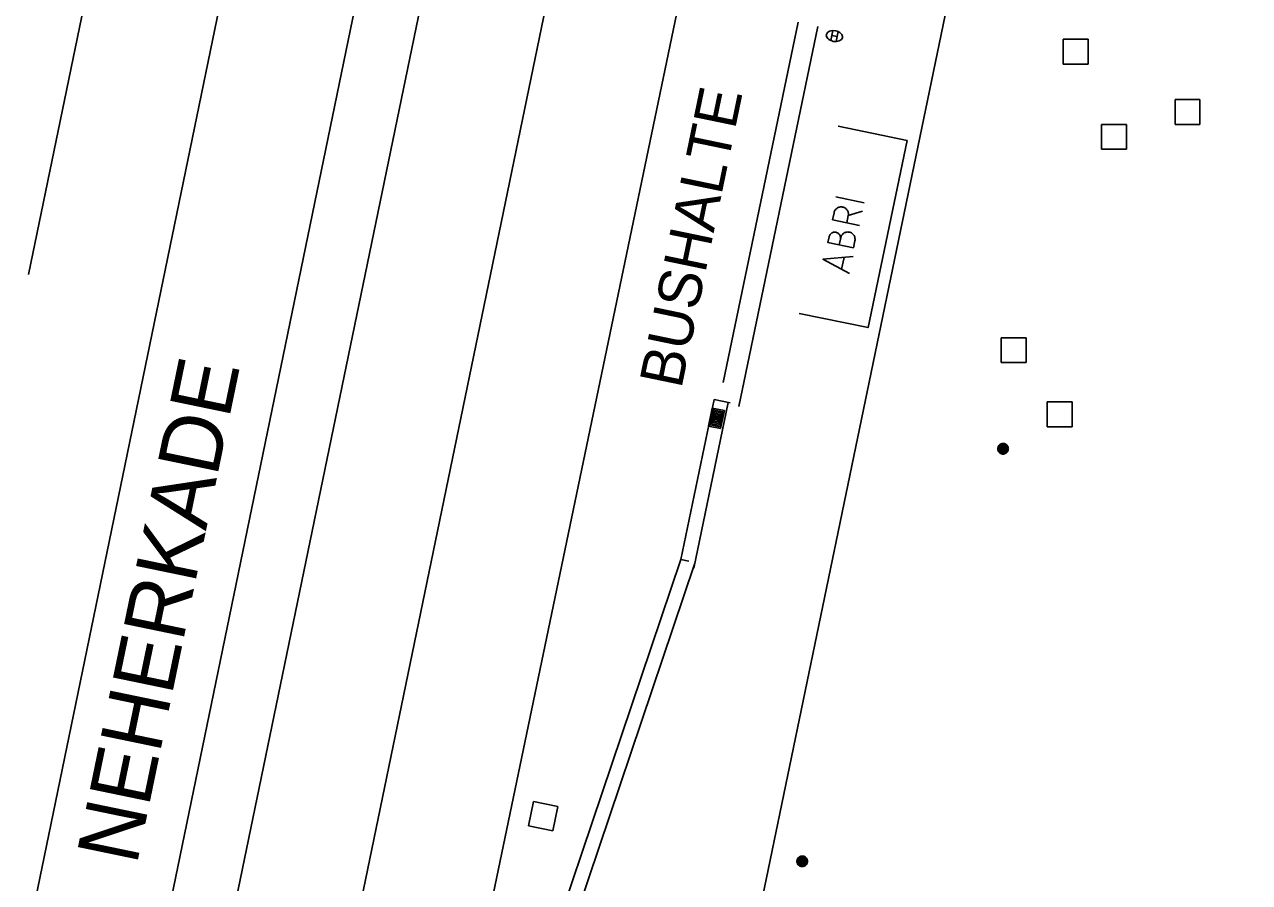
# Model space of a CAD drawing. Extents: x 81065 to 81486, y 452384 to 452681.
# Drawn here: x 81361.83 to 81391.8, y 452616.85 to 452637.83 of the extents above; entities that cross this region are included whole.
import ezdxf

# ---------------------------------------------------------------- set-up
doc = ezdxf.new("R2010")
doc.units = 0
for name, color, linetype in [('B-BH-AL-TOPOGRAFIE_STRAATNAAM-S', 7, 'Continuous'), ('B-BH-GR-BOOM-S', 7, 'Continuous'), ('B-BH-IE-MEUBILAIR_WEGMEUBILAIR_ABRI-S', 7, 'Continuous'), ('B-BH-RI-GWA_RIOOLPUT-S', 7, 'Continuous'), ('B-BH-VH-KANTOPSLUITING-GV', 7, 'Continuous'), ('B-BH-VW-HALTEPAAL-S', 7, 'Continuous'), ('B-SRI-KOLK_COMBINATIE-S', 7, 'Continuous'), ('B-WE-VW-MARKERING-G', 7, 'Continuous'), ('B-WE-VW-MARKERING_LANGS_STREEP_13_010-G', 7, 'Continuous'), ('B-WE-VW-MARKERING_LANGS_STREEP_DOORGETROKKEN_010-G', 7, 'Continuous')]:
    doc.layers.add(name, color=color, linetype=linetype)

msp = doc.modelspace()

# ---------------------------------------------------------------- linework, layer by layer
at = {"layer": 'B-BH-GR-BOOM-S'}
for points in [[(81385.639, 452627.458), (81385.64, 452627.444), (81385.642, 452627.431), (81385.646, 452627.418), (81385.65, 452627.405), (81385.656, 452627.393), (81385.664, 452627.382), (81385.672, 452627.371), (81385.682, 452627.362), (81385.692, 452627.353), (81385.704, 452627.346), (81385.716, 452627.34), (81385.728, 452627.335), (81385.741, 452627.332), (81385.755, 452627.329), (81385.768, 452627.329), (81385.782, 452627.329), (81385.795, 452627.332), (81385.808, 452627.335), (81385.821, 452627.34), (81385.833, 452627.346), (81385.844, 452627.353), (81385.854, 452627.362), (81385.864, 452627.371), (81385.872, 452627.382), (81385.88, 452627.393), (81385.886, 452627.405), (81385.891, 452627.418), (81385.894, 452627.431), (81385.896, 452627.444), (81385.897, 452627.458), (81385.896, 452627.471), (81385.894, 452627.484), (81385.891, 452627.497), (81385.886, 452627.51), (81385.88, 452627.522), (81385.872, 452627.533), (81385.864, 452627.544), (81385.854, 452627.553), (81385.844, 452627.562), (81385.833, 452627.569), (81385.821, 452627.575), (81385.808, 452627.58), (81385.795, 452627.584), (81385.782, 452627.586), (81385.768, 452627.586), (81385.755, 452627.586), (81385.741, 452627.584), (81385.728, 452627.58), (81385.716, 452627.575), (81385.704, 452627.569), (81385.692, 452627.562), (81385.682, 452627.553), (81385.672, 452627.544), (81385.664, 452627.533), (81385.656, 452627.522), (81385.65, 452627.51), (81385.646, 452627.497), (81385.642, 452627.484), (81385.64, 452627.471), (81385.639, 452627.458)], [(81385.664, 452627.458), (81385.664, 452627.447), (81385.666, 452627.436), (81385.669, 452627.425), (81385.673, 452627.415), (81385.678, 452627.405), (81385.684, 452627.396), (81385.691, 452627.388), (81385.698, 452627.38), (81385.707, 452627.373), (81385.716, 452627.367), (81385.726, 452627.362), (81385.736, 452627.358), (81385.746, 452627.355), (81385.757, 452627.354), (81385.768, 452627.353), (81385.779, 452627.354), (81385.79, 452627.355), (81385.8, 452627.358), (81385.811, 452627.362), (81385.82, 452627.367), (81385.829, 452627.373), (81385.838, 452627.38), (81385.846, 452627.388), (81385.853, 452627.396), (81385.859, 452627.405), (81385.864, 452627.415), (81385.867, 452627.425), (81385.87, 452627.436), (81385.872, 452627.447), (81385.873, 452627.458), (81385.872, 452627.469), (81385.87, 452627.479), (81385.867, 452627.49), (81385.864, 452627.5), (81385.859, 452627.51), (81385.853, 452627.519), (81385.846, 452627.527), (81385.838, 452627.535), (81385.829, 452627.542), (81385.82, 452627.548), (81385.811, 452627.553), (81385.8, 452627.557), (81385.79, 452627.56), (81385.779, 452627.561), (81385.768, 452627.562), (81385.757, 452627.561), (81385.746, 452627.56), (81385.736, 452627.557), (81385.726, 452627.553), (81385.716, 452627.548), (81385.707, 452627.542), (81385.698, 452627.535), (81385.691, 452627.527), (81385.684, 452627.519), (81385.678, 452627.51), (81385.673, 452627.5), (81385.669, 452627.49), (81385.666, 452627.479), (81385.664, 452627.469), (81385.664, 452627.458)], [(81385.687, 452627.458), (81385.687, 452627.449), (81385.688, 452627.441), (81385.691, 452627.432), (81385.694, 452627.424), (81385.697, 452627.417), (81385.702, 452627.41), (81385.708, 452627.403), (81385.713, 452627.397), (81385.72, 452627.392), (81385.727, 452627.387), (81385.735, 452627.383), (81385.743, 452627.38), (81385.751, 452627.378), (81385.76, 452627.376), (81385.768, 452627.376), (81385.777, 452627.376), (81385.785, 452627.378), (81385.793, 452627.38), (81385.801, 452627.383), (81385.809, 452627.387), (81385.816, 452627.392), (81385.823, 452627.397), (81385.829, 452627.403), (81385.834, 452627.41), (81385.839, 452627.417), (81385.843, 452627.424), (81385.846, 452627.432), (81385.848, 452627.441), (81385.849, 452627.449), (81385.85, 452627.458), (81385.849, 452627.466), (81385.848, 452627.474), (81385.846, 452627.483), (81385.843, 452627.491), (81385.839, 452627.498), (81385.834, 452627.505), (81385.829, 452627.512), (81385.823, 452627.518), (81385.816, 452627.524), (81385.809, 452627.528), (81385.801, 452627.532), (81385.793, 452627.535), (81385.785, 452627.537), (81385.777, 452627.539), (81385.768, 452627.539), (81385.76, 452627.539), (81385.751, 452627.537), (81385.743, 452627.535), (81385.735, 452627.532), (81385.727, 452627.528), (81385.72, 452627.524), (81385.713, 452627.518), (81385.708, 452627.512), (81385.702, 452627.505), (81385.697, 452627.498), (81385.694, 452627.491), (81385.691, 452627.483), (81385.688, 452627.474), (81385.687, 452627.466), (81385.687, 452627.458)], [(81385.709, 452627.458), (81385.71, 452627.451), (81385.711, 452627.445), (81385.712, 452627.439), (81385.714, 452627.434), (81385.717, 452627.428), (81385.721, 452627.423), (81385.724, 452627.418), (81385.729, 452627.414), (81385.734, 452627.41), (81385.739, 452627.407), (81385.744, 452627.404), (81385.75, 452627.402), (81385.756, 452627.4), (81385.762, 452627.399), (81385.768, 452627.399), (81385.774, 452627.399), (81385.78, 452627.4), (81385.786, 452627.402), (81385.792, 452627.404), (81385.797, 452627.407), (81385.803, 452627.41), (81385.807, 452627.414), (81385.812, 452627.418), (81385.816, 452627.423), (81385.819, 452627.428), (81385.822, 452627.434), (81385.824, 452627.439), (81385.826, 452627.445), (81385.827, 452627.451), (81385.827, 452627.458), (81385.827, 452627.464), (81385.826, 452627.47), (81385.824, 452627.476), (81385.822, 452627.481), (81385.819, 452627.487), (81385.816, 452627.492), (81385.812, 452627.497), (81385.807, 452627.501), (81385.803, 452627.505), (81385.797, 452627.508), (81385.792, 452627.511), (81385.786, 452627.513), (81385.78, 452627.515), (81385.774, 452627.516), (81385.768, 452627.516), (81385.762, 452627.516), (81385.756, 452627.515), (81385.75, 452627.513), (81385.744, 452627.511), (81385.739, 452627.508), (81385.734, 452627.505), (81385.729, 452627.501), (81385.724, 452627.497), (81385.721, 452627.492), (81385.717, 452627.487), (81385.714, 452627.481), (81385.712, 452627.476), (81385.711, 452627.47), (81385.71, 452627.464), (81385.709, 452627.458)], [(81385.732, 452627.458), (81385.733, 452627.454), (81385.733, 452627.45), (81385.734, 452627.447), (81385.735, 452627.443), (81385.737, 452627.44), (81385.739, 452627.437), (81385.742, 452627.434), (81385.744, 452627.431), (81385.747, 452627.429), (81385.75, 452627.427), (81385.754, 452627.425), (81385.757, 452627.424), (81385.761, 452627.423), (81385.764, 452627.422), (81385.768, 452627.422), (81385.772, 452627.422), (81385.775, 452627.423), (81385.779, 452627.424), (81385.783, 452627.425), (81385.786, 452627.427), (81385.789, 452627.429), (81385.792, 452627.431), (81385.795, 452627.434), (81385.797, 452627.437), (81385.799, 452627.44), (81385.801, 452627.443), (81385.802, 452627.447), (81385.803, 452627.45), (81385.804, 452627.454), (81385.804, 452627.458), (81385.804, 452627.461), (81385.803, 452627.465), (81385.802, 452627.469), (81385.801, 452627.472), (81385.799, 452627.475), (81385.797, 452627.479), (81385.795, 452627.482), (81385.792, 452627.484), (81385.789, 452627.487), (81385.786, 452627.489), (81385.783, 452627.49), (81385.779, 452627.492), (81385.775, 452627.493), (81385.772, 452627.493), (81385.768, 452627.493), (81385.764, 452627.493), (81385.761, 452627.493), (81385.757, 452627.492), (81385.754, 452627.49), (81385.75, 452627.489), (81385.747, 452627.487), (81385.744, 452627.484), (81385.742, 452627.482), (81385.739, 452627.479), (81385.737, 452627.475), (81385.735, 452627.472), (81385.734, 452627.469), (81385.733, 452627.465), (81385.733, 452627.461), (81385.732, 452627.458)], [(81385.755, 452627.458), (81385.755, 452627.456), (81385.755, 452627.455), (81385.756, 452627.454), (81385.756, 452627.452), (81385.757, 452627.451), (81385.758, 452627.45), (81385.759, 452627.449), (81385.76, 452627.448), (81385.76, 452627.447), (81385.762, 452627.446), (81385.763, 452627.446), (81385.764, 452627.445), (81385.765, 452627.445), (81385.767, 452627.445), (81385.768, 452627.445), (81385.77, 452627.445), (81385.771, 452627.445), (81385.772, 452627.445), (81385.773, 452627.446), (81385.775, 452627.446), (81385.776, 452627.447), (81385.777, 452627.448), (81385.778, 452627.449), (81385.779, 452627.45), (81385.779, 452627.451), (81385.78, 452627.452), (81385.78, 452627.454), (81385.781, 452627.455), (81385.781, 452627.456), (81385.781, 452627.458), (81385.781, 452627.459), (81385.781, 452627.46), (81385.78, 452627.462), (81385.78, 452627.463), (81385.779, 452627.464), (81385.779, 452627.465), (81385.778, 452627.466), (81385.777, 452627.467), (81385.776, 452627.468), (81385.775, 452627.469), (81385.773, 452627.469), (81385.772, 452627.47), (81385.771, 452627.47), (81385.77, 452627.47), (81385.768, 452627.47), (81385.767, 452627.47), (81385.765, 452627.47), (81385.764, 452627.47), (81385.763, 452627.469), (81385.762, 452627.469), (81385.76, 452627.468), (81385.76, 452627.467), (81385.759, 452627.466), (81385.758, 452627.465), (81385.757, 452627.464), (81385.756, 452627.463), (81385.756, 452627.462), (81385.755, 452627.46), (81385.755, 452627.459), (81385.755, 452627.458)], [(81380.726, 452617.367), (81380.727, 452617.353), (81380.729, 452617.34), (81380.733, 452617.327), (81380.737, 452617.314), (81380.743, 452617.302), (81380.751, 452617.291), (81380.759, 452617.28), (81380.769, 452617.271), (81380.779, 452617.262), (81380.791, 452617.255), (81380.803, 452617.249), (81380.815, 452617.244), (81380.828, 452617.241), (81380.842, 452617.238), (81380.855, 452617.238), (81380.869, 452617.238), (81380.882, 452617.241), (81380.895, 452617.244), (81380.908, 452617.249), (81380.92, 452617.255), (81380.931, 452617.262), (81380.941, 452617.271), (81380.951, 452617.28), (81380.959, 452617.291), (81380.967, 452617.302), (81380.973, 452617.314), (81380.978, 452617.327), (81380.981, 452617.34), (81380.983, 452617.353), (81380.984, 452617.367), (81380.983, 452617.38), (81380.981, 452617.393), (81380.978, 452617.406), (81380.973, 452617.419), (81380.967, 452617.431), (81380.959, 452617.442), (81380.951, 452617.453), (81380.941, 452617.462), (81380.931, 452617.471), (81380.92, 452617.478), (81380.908, 452617.484), (81380.895, 452617.489), (81380.882, 452617.493), (81380.869, 452617.495), (81380.855, 452617.495), (81380.842, 452617.495), (81380.828, 452617.493), (81380.815, 452617.489), (81380.803, 452617.484), (81380.791, 452617.478), (81380.779, 452617.471), (81380.769, 452617.462), (81380.759, 452617.453), (81380.751, 452617.442), (81380.743, 452617.431), (81380.737, 452617.419), (81380.733, 452617.406), (81380.729, 452617.393), (81380.727, 452617.38), (81380.726, 452617.367)], [(81380.751, 452617.367), (81380.751, 452617.356), (81380.753, 452617.345), (81380.756, 452617.334), (81380.76, 452617.324), (81380.765, 452617.314), (81380.771, 452617.305), (81380.778, 452617.297), (81380.785, 452617.289), (81380.794, 452617.282), (81380.803, 452617.276), (81380.813, 452617.271), (81380.823, 452617.267), (81380.833, 452617.264), (81380.844, 452617.263), (81380.855, 452617.262), (81380.866, 452617.263), (81380.877, 452617.264), (81380.887, 452617.267), (81380.898, 452617.271), (81380.907, 452617.276), (81380.916, 452617.282), (81380.925, 452617.289), (81380.933, 452617.297), (81380.94, 452617.305), (81380.946, 452617.314), (81380.951, 452617.324), (81380.954, 452617.334), (81380.957, 452617.345), (81380.959, 452617.356), (81380.96, 452617.367), (81380.959, 452617.378), (81380.957, 452617.388), (81380.954, 452617.399), (81380.951, 452617.409), (81380.946, 452617.419), (81380.94, 452617.428), (81380.933, 452617.436), (81380.925, 452617.444), (81380.916, 452617.451), (81380.907, 452617.457), (81380.898, 452617.462), (81380.887, 452617.466), (81380.877, 452617.469), (81380.866, 452617.47), (81380.855, 452617.471), (81380.844, 452617.47), (81380.833, 452617.469), (81380.823, 452617.466), (81380.813, 452617.462), (81380.803, 452617.457), (81380.794, 452617.451), (81380.785, 452617.444), (81380.778, 452617.436), (81380.771, 452617.428), (81380.765, 452617.419), (81380.76, 452617.409), (81380.756, 452617.399), (81380.753, 452617.388), (81380.751, 452617.378), (81380.751, 452617.367)], [(81380.774, 452617.367), (81380.774, 452617.358), (81380.775, 452617.35), (81380.778, 452617.341), (81380.781, 452617.333), (81380.784, 452617.326), (81380.789, 452617.319), (81380.795, 452617.312), (81380.8, 452617.306), (81380.807, 452617.301), (81380.814, 452617.296), (81380.822, 452617.292), (81380.83, 452617.289), (81380.838, 452617.287), (81380.847, 452617.285), (81380.855, 452617.285), (81380.864, 452617.285), (81380.872, 452617.287), (81380.88, 452617.289), (81380.888, 452617.292), (81380.896, 452617.296), (81380.903, 452617.301), (81380.91, 452617.306), (81380.916, 452617.312), (81380.921, 452617.319), (81380.926, 452617.326), (81380.93, 452617.333), (81380.933, 452617.341), (81380.935, 452617.35), (81380.936, 452617.358), (81380.937, 452617.367), (81380.936, 452617.375), (81380.935, 452617.383), (81380.933, 452617.392), (81380.93, 452617.4), (81380.926, 452617.407), (81380.921, 452617.414), (81380.916, 452617.421), (81380.91, 452617.427), (81380.903, 452617.433), (81380.896, 452617.437), (81380.888, 452617.441), (81380.88, 452617.444), (81380.872, 452617.446), (81380.864, 452617.448), (81380.855, 452617.448), (81380.847, 452617.448), (81380.838, 452617.446), (81380.83, 452617.444), (81380.822, 452617.441), (81380.814, 452617.437), (81380.807, 452617.433), (81380.8, 452617.427), (81380.795, 452617.421), (81380.789, 452617.414), (81380.784, 452617.407), (81380.781, 452617.4), (81380.778, 452617.392), (81380.775, 452617.383), (81380.774, 452617.375), (81380.774, 452617.367)], [(81380.796, 452617.367), (81380.797, 452617.36), (81380.798, 452617.354), (81380.799, 452617.348), (81380.801, 452617.343), (81380.804, 452617.337), (81380.808, 452617.332), (81380.811, 452617.327), (81380.816, 452617.323), (81380.821, 452617.319), (81380.826, 452617.316), (81380.831, 452617.313), (81380.837, 452617.311), (81380.843, 452617.309), (81380.849, 452617.308), (81380.855, 452617.308), (81380.861, 452617.308), (81380.867, 452617.309), (81380.873, 452617.311), (81380.879, 452617.313), (81380.884, 452617.316), (81380.89, 452617.319), (81380.894, 452617.323), (81380.899, 452617.327), (81380.903, 452617.332), (81380.906, 452617.337), (81380.909, 452617.343), (81380.911, 452617.348), (81380.913, 452617.354), (81380.914, 452617.36), (81380.914, 452617.367), (81380.914, 452617.373), (81380.913, 452617.379), (81380.911, 452617.385), (81380.909, 452617.39), (81380.906, 452617.396), (81380.903, 452617.401), (81380.899, 452617.406), (81380.894, 452617.41), (81380.89, 452617.414), (81380.884, 452617.417), (81380.879, 452617.42), (81380.873, 452617.422), (81380.867, 452617.424), (81380.861, 452617.425), (81380.855, 452617.425), (81380.849, 452617.425), (81380.843, 452617.424), (81380.837, 452617.422), (81380.831, 452617.42), (81380.826, 452617.417), (81380.821, 452617.414), (81380.816, 452617.41), (81380.811, 452617.406), (81380.808, 452617.401), (81380.804, 452617.396), (81380.801, 452617.39), (81380.799, 452617.385), (81380.798, 452617.379), (81380.797, 452617.373), (81380.796, 452617.367)], [(81380.819, 452617.367), (81380.82, 452617.363), (81380.82, 452617.359), (81380.821, 452617.356), (81380.822, 452617.352), (81380.824, 452617.349), (81380.826, 452617.346), (81380.829, 452617.343), (81380.831, 452617.34), (81380.834, 452617.338), (81380.837, 452617.336), (81380.841, 452617.334), (81380.844, 452617.333), (81380.848, 452617.332), (81380.851, 452617.331), (81380.855, 452617.331), (81380.859, 452617.331), (81380.862, 452617.332), (81380.866, 452617.333), (81380.87, 452617.334), (81380.873, 452617.336), (81380.876, 452617.338), (81380.879, 452617.34), (81380.882, 452617.343), (81380.884, 452617.346), (81380.886, 452617.349), (81380.888, 452617.352), (81380.889, 452617.356), (81380.89, 452617.359), (81380.891, 452617.363), (81380.891, 452617.367), (81380.891, 452617.37), (81380.89, 452617.374), (81380.889, 452617.378), (81380.888, 452617.381), (81380.886, 452617.384), (81380.884, 452617.388), (81380.882, 452617.391), (81380.879, 452617.393), (81380.876, 452617.396), (81380.873, 452617.398), (81380.87, 452617.399), (81380.866, 452617.401), (81380.862, 452617.402), (81380.859, 452617.402), (81380.855, 452617.402), (81380.851, 452617.402), (81380.848, 452617.402), (81380.844, 452617.401), (81380.841, 452617.399), (81380.837, 452617.398), (81380.834, 452617.396), (81380.831, 452617.393), (81380.829, 452617.391), (81380.826, 452617.388), (81380.824, 452617.384), (81380.822, 452617.381), (81380.821, 452617.378), (81380.82, 452617.374), (81380.82, 452617.37), (81380.819, 452617.367)], [(81380.842, 452617.367), (81380.842, 452617.365), (81380.842, 452617.364), (81380.843, 452617.363), (81380.843, 452617.361), (81380.844, 452617.36), (81380.845, 452617.359), (81380.846, 452617.358), (81380.847, 452617.357), (81380.847, 452617.356), (81380.849, 452617.355), (81380.85, 452617.355), (81380.851, 452617.354), (81380.852, 452617.354), (81380.854, 452617.354), (81380.855, 452617.354), (81380.857, 452617.354), (81380.858, 452617.354), (81380.859, 452617.354), (81380.86, 452617.355), (81380.862, 452617.355), (81380.863, 452617.356), (81380.864, 452617.357), (81380.865, 452617.358), (81380.866, 452617.359), (81380.866, 452617.36), (81380.867, 452617.361), (81380.867, 452617.363), (81380.868, 452617.364), (81380.868, 452617.365), (81380.868, 452617.367), (81380.868, 452617.368), (81380.868, 452617.369), (81380.867, 452617.371), (81380.867, 452617.372), (81380.866, 452617.373), (81380.866, 452617.374), (81380.865, 452617.375), (81380.864, 452617.376), (81380.863, 452617.377), (81380.862, 452617.378), (81380.86, 452617.378), (81380.859, 452617.379), (81380.858, 452617.379), (81380.857, 452617.379), (81380.855, 452617.379), (81380.854, 452617.379), (81380.852, 452617.379), (81380.851, 452617.379), (81380.85, 452617.378), (81380.849, 452617.378), (81380.847, 452617.377), (81380.847, 452617.376), (81380.846, 452617.375), (81380.845, 452617.374), (81380.844, 452617.373), (81380.843, 452617.372), (81380.843, 452617.371), (81380.842, 452617.369), (81380.842, 452617.368), (81380.842, 452617.367)]]:
    msp.add_lwpolyline(points, dxfattribs=at)
at = {"layer": 'B-BH-IE-MEUBILAIR_WEGMEUBILAIR_ABRI-S'}
for p, q in [((81381.678, 452633.62), (81382.372, 452633.475)), ((81381.981, 452633.159), (81381.945, 452632.985)), ((81382.329, 452633.267), (81381.981, 452633.159)), ((81381.796, 452632.618), (81381.76, 452632.445)), ((81381.816, 452631.846), (81381.877, 452632.138))]:
    msp.add_line(p, q, dxfattribs=at)
for points in [[(81380.784, 452630.769), (81382.466, 452630.419), (81383.419, 452634.996), (81381.737, 452635.346)], [(81381.634, 452633.231), (81381.598, 452633.057), (81382.257, 452632.92)], [(81381.981, 452633.158), (81381.984, 452633.177), (81381.984, 452633.195), (81381.983, 452633.214), (81381.98, 452633.232), (81381.976, 452633.25), (81381.969, 452633.267), (81381.96, 452633.284), (81381.95, 452633.299), (81381.938, 452633.314), (81381.925, 452633.327), (81381.911, 452633.338), (81381.895, 452633.348), (81381.879, 452633.357), (81381.861, 452633.363), (81381.843, 452633.368), (81381.825, 452633.371), (81381.806, 452633.372), (81381.788, 452633.371), (81381.77, 452633.368), (81381.752, 452633.363), (81381.734, 452633.356), (81381.718, 452633.348), (81381.702, 452633.337), (81381.688, 452633.326), (81381.675, 452633.313), (81381.663, 452633.298), (81381.653, 452633.283), (81381.645, 452633.266), (81381.638, 452633.249), (81381.634, 452633.231)], [(81381.511, 452632.641), (81381.482, 452632.502), (81382.107, 452632.372), (81382.143, 452632.546)], [(81381.789, 452632.583), (81381.791, 452632.598), (81381.792, 452632.613), (81381.791, 452632.627), (81381.788, 452632.642), (81381.784, 452632.656), (81381.779, 452632.67), (81381.772, 452632.683), (81381.764, 452632.696), (81381.755, 452632.707), (81381.744, 452632.718), (81381.733, 452632.727), (81381.72, 452632.735), (81381.707, 452632.742), (81381.693, 452632.747), (81381.679, 452632.751), (81381.664, 452632.753), (81381.649, 452632.754), (81381.634, 452632.753), (81381.62, 452632.751), (81381.605, 452632.747), (81381.592, 452632.741), (81381.578, 452632.735), (81381.566, 452632.726), (81381.555, 452632.717), (81381.544, 452632.706), (81381.535, 452632.695), (81381.527, 452632.682), (81381.52, 452632.669), (81381.515, 452632.655), (81381.511, 452632.641)], [(81382.143, 452632.546), (81382.146, 452632.564), (81382.146, 452632.583), (81382.145, 452632.601), (81382.142, 452632.619), (81382.138, 452632.637), (81382.131, 452632.655), (81382.122, 452632.671), (81382.112, 452632.687), (81382.1, 452632.701), (81382.087, 452632.714), (81382.073, 452632.726), (81382.057, 452632.736), (81382.041, 452632.744), (81382.023, 452632.751), (81382.005, 452632.755), (81381.987, 452632.758), (81381.969, 452632.759), (81381.95, 452632.758), (81381.932, 452632.755), (81381.914, 452632.75), (81381.897, 452632.743), (81381.88, 452632.735), (81381.865, 452632.725), (81381.85, 452632.713), (81381.837, 452632.7), (81381.825, 452632.685), (81381.815, 452632.67), (81381.807, 452632.653), (81381.801, 452632.636), (81381.796, 452632.618)], [(81382.011, 452631.741), (81381.361, 452632.093), (81382.098, 452632.157)]]:
    msp.add_lwpolyline(points, dxfattribs=at)
at = {"layer": 'B-BH-RI-GWA_RIOOLPUT-S'}
for p, q in [((81387.849, 452637.472), (81387.241, 452637.472)), ((81387.241, 452637.472), (81387.241, 452636.865)), ((81387.849, 452636.865), (81387.849, 452637.472)), ((81387.241, 452636.865), (81387.849, 452636.865)), ((81390.582, 452635.996), (81389.974, 452635.996)), ((81389.974, 452635.996), (81389.974, 452635.389)), ((81390.582, 452635.389), (81390.582, 452635.996)), ((81388.785, 452635.39), (81388.177, 452635.39)), ((81388.177, 452635.39), (81388.177, 452634.783)), ((81388.785, 452634.783), (81388.785, 452635.39)), ((81389.974, 452635.389), (81390.582, 452635.389)), ((81388.177, 452634.783), (81388.785, 452634.783)), ((81386.332, 452630.172), (81385.724, 452630.172)), ((81385.724, 452630.172), (81385.724, 452629.565)), ((81386.332, 452629.565), (81386.332, 452630.172)), ((81385.724, 452629.565), (81386.332, 452629.565)), ((81387.458, 452628.603), (81386.85, 452628.603)), ((81386.85, 452628.603), (81386.85, 452627.996)), ((81387.458, 452627.996), (81387.458, 452628.603)), ((81386.85, 452627.996), (81387.458, 452627.996)), ((81374.284, 452618.828), (81374.16, 452618.233)), ((81374.878, 452618.704), (81374.284, 452618.828)), ((81374.754, 452618.109), (81374.878, 452618.704)), ((81374.16, 452618.233), (81374.754, 452618.109))]:
    msp.add_line(p, q, dxfattribs=at)
at = {"layer": 'B-BH-VH-KANTOPSLUITING-GV'}
for p, q in [((81356.044, 452571.02), (81377.517, 452675.08)), ((81357.638, 452571.02), (81376.98, 452664.753)), ((81378.919, 452629.075), (81380.753, 452637.887)), ((81377.885, 452624.747), (81378.7, 452628.663)), ((81378.7, 452628.663), (81379.092, 452628.582)), ((81379.096, 452628.301), (81379.096, 452628.301)), ((81369.874, 452600.981), (81377.885, 452624.747)), ((81377.885, 452624.747), (81378.081, 452624.706))]:
    msp.add_line(p, q, dxfattribs=at)
msp.add_lwpolyline([(81391.796, 452675.08), (81385.964, 452645.863), (81376.456, 452599.952)], dxfattribs=at)
at = {"layer": 'B-BH-VW-HALTEPAAL-S'}
for p, q in [((81381.603, 452637.689), (81381.551, 452637.442)), ((81381.733, 452637.662), (81381.682, 452637.415)), ((81381.577, 452637.566), (81381.707, 452637.538))]:
    msp.add_line(p, q, dxfattribs=at)
msp.add_ellipse((81381.642, 452637.552), major_axis=(0.196, -0.041), ratio=0.666667, dxfattribs=at)
at = {"layer": 'B-SRI-KOLK_COMBINATIE-S'}
for points in [[(81378.859, 452627.951), (81378.95, 452628.392), (81378.656, 452628.452), (81378.565, 452628.012)], [(81378.836, 452627.991), (81378.913, 452628.363), (81378.678, 452628.412), (81378.601, 452628.04)], [(81378.814, 452628.032), (81378.877, 452628.335), (81378.7, 452628.372), (81378.638, 452628.068)], [(81378.792, 452628.072), (81378.84, 452628.307), (81378.723, 452628.331), (81378.674, 452628.096)], [(81378.769, 452628.112), (81378.804, 452628.279), (81378.745, 452628.291), (81378.711, 452628.124)], [(81378.747, 452628.153), (81378.767, 452628.251), (81378.767, 452628.251), (81378.747, 452628.153)]]:
    msp.add_lwpolyline(points, close=True, dxfattribs=at)
at = {"layer": 'B-WE-VW-MARKERING-G'}
for p, q in [((81379.304, 452628.494), (81381.237, 452637.781)), ((81378.201, 452624.533), (81379.044, 452628.591)), ((81370.206, 452600.869), (81378.217, 452624.635))]:
    msp.add_line(p, q, dxfattribs=at)
at = {"layer": 'B-WE-VW-MARKERING_LANGS_STREEP_13_010-G'}
for p, q in [((81352.725, 452571.02), (81374.198, 452675.08)), ((81370.319, 452672.362), (81361.932, 452631.717)), ((81360.701, 452571.02), (81379.855, 452663.838))]:
    msp.add_line(p, q, dxfattribs=at)
at = {"layer": 'B-WE-VW-MARKERING_LANGS_STREEP_DOORGETROKKEN_010-G'}
msp.add_line((81370.194, 452601.649), (81380.698, 452652.116), dxfattribs=at)

# ---------------------------------------------------------------- texts
at = {"layer": 'B-BH-AL-TOPOGRAFIE_STRAATNAAM-S'}
for s, height, p in [('BUSHALTE', 1.05, (81377.896, 452628.902)), ('NEHERKADE', 1.5, (81364.573, 452617.25))]:
    msp.add_text(s, height=height, rotation=78.3038, dxfattribs=at).set_placement(p)

doc.saveas('drawing.dxf')
